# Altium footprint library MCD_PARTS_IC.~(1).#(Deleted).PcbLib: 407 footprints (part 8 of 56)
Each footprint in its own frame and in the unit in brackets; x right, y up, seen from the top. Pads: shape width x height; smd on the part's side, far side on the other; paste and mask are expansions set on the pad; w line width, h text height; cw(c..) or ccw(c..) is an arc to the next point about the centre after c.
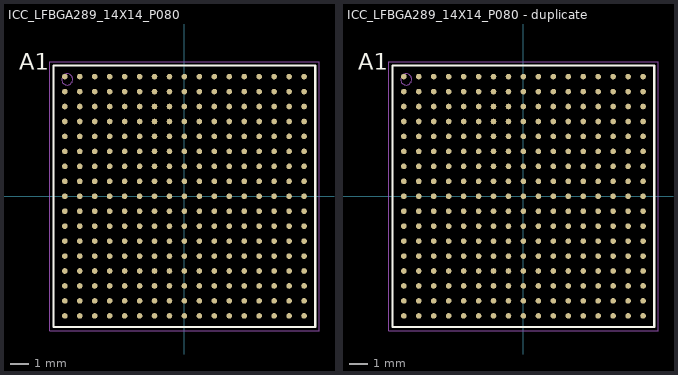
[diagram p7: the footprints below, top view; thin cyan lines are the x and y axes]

## ICC_LFBGA289_14X14_P080 [mm] "MCD-02237"
height 1.7
pads (289):
  round 0.3 smd mask+0.05: A1(-6.4,6.4) A2(-5.6,6.4) A3(-4.8,6.4) A4(-4,6.4) A5(-3.2,6.4) A6(-2.4,6.4) A7(-1.6,6.4) A8(-0.8,6.4) A9(0,6.4) A10(0.8,6.4) A11(1.6,6.4) A12(2.4,6.4) A13(3.2,6.4) A14(4,6.4) A15(4.8,6.4) A16(5.6,6.4) A17(6.4,6.4) B1(-6.4,5.6) B2(-5.6,5.6) B3(-4.8,5.6) B4(-4,5.6) B5(-3.2,5.6) B6(-2.4,5.6) B7(-1.6,5.6) B8(-0.8,5.6) B9(0,5.6) B10(0.8,5.6) B11(1.6,5.6) B12(2.4,5.6) B13(3.2,5.6) B14(4,5.6) B15(4.8,5.6) B16(5.6,5.6) B17(6.4,5.6) C1(-6.4,4.8) C2(-5.6,4.8) C3(-4.8,4.8) C4(-4,4.8) C5(-3.2,4.8) C6(-2.4,4.8) C7(-1.6,4.8) C8(-0.8,4.8) C9(0,4.8) C10(0.8,4.8) C11(1.6,4.8) C12(2.4,4.8) C13(3.2,4.8) C14(4,4.8) C15(4.8,4.8) C16(5.6,4.8) C17(6.4,4.8) D1(-6.4,4) D2(-5.6,4) D3(-4.8,4) D4(-4,4) D5(-3.2,4) D6(-2.4,4) D7(-1.6,4) D8(-0.8,4) D9(0,4) D10(0.8,4) D11(1.6,4) D12(2.4,4) D13(3.2,4) D14(4,4) D15(4.8,4) D16(5.6,4) D17(6.4,4) E1(-6.4,3.2) E2(-5.6,3.2) E3(-4.8,3.2) E4(-4,3.2) E5(-3.2,3.2) E6(-2.4,3.2) E7(-1.6,3.2) E8(-0.8,3.2) E9(0,3.2) E10(0.8,3.2) E11(1.6,3.2) E12(2.4,3.2) E13(3.2,3.2) E14(4,3.2) E15(4.8,3.2) E16(5.6,3.2) E17(6.4,3.2) F1(-6.4,2.4) F2(-5.6,2.4) F3(-4.8,2.4) F4(-4,2.4) F5(-3.2,2.4) F6(-2.4,2.4) F7(-1.6,2.4) F8(-0.8,2.4) F9(0,2.4) F10(0.8,2.4) F11(1.6,2.4) F12(2.4,2.4) F13(3.2,2.4) F14(4,2.4) F15(4.8,2.4) F16(5.6,2.4) F17(6.4,2.4) G1(-6.4,1.6) G2(-5.6,1.6) G3(-4.8,1.6) G4(-4,1.6) G5(-3.2,1.6) G6(-2.4,1.6) G7(-1.6,1.6) G8(-0.8,1.6) G9(0,1.6) G10(0.8,1.6) G11(1.6,1.6) G12(2.4,1.6) G13(3.2,1.6) G14(4,1.6) G15(4.8,1.6) G16(5.6,1.6) G17(6.4,1.6) H1(-6.4,0.8) H2(-5.6,0.8) H3(-4.8,0.8) H4(-4,0.8) H5(-3.2,0.8) H6(-2.4,0.8) H7(-1.6,0.8) H8(-0.8,0.8) H9(0,0.8) H10(0.8,0.8) H11(1.6,0.8) H12(2.4,0.8) H13(3.2,0.8) H14(4,0.8) H15(4.8,0.8) H16(5.6,0.8) H17(6.4,0.8) J1(-6.4,0) J2(-5.6,0) J3(-4.8,0) J4(-4,0) J5(-3.2,0) J6(-2.4,0) J7(-1.6,0) J8(-0.8,0) J9(0,0) J10(0.8,0) J11(1.6,0) J12(2.4,0) J13(3.2,0) J14(4,0) J15(4.8,0) J16(5.6,0) J17(6.4,0) K1(-6.4,-0.8) K2(-5.6,-0.8) K3(-4.8,-0.8) K4(-4,-0.8) K5(-3.2,-0.8) K6(-2.4,-0.8) K7(-1.6,-0.8) K8(-0.8,-0.8) K9(0,-0.8) K10(0.8,-0.8) K11(1.6,-0.8) K12(2.4,-0.8) K13(3.2,-0.8) K14(4,-0.8) K15(4.8,-0.8) K16(5.6,-0.8) K17(6.4,-0.8) L1(-6.4,-1.6) L2(-5.6,-1.6) L3(-4.8,-1.6) L4(-4,-1.6) L5(-3.2,-1.6) L6(-2.4,-1.6) L7(-1.6,-1.6) L8(-0.8,-1.6) L9(0,-1.6) L10(0.8,-1.6) L11(1.6,-1.6) L12(2.4,-1.6) L13(3.2,-1.6) L14(4,-1.6) L15(4.8,-1.6) L16(5.6,-1.6) L17(6.4,-1.6) M1(-6.4,-2.4) M2(-5.6,-2.4) M3(-4.8,-2.4) M4(-4,-2.4) M5(-3.2,-2.4) M6(-2.4,-2.4) M7(-1.6,-2.4) M8(-0.8,-2.4) M9(0,-2.4) M10(0.8,-2.4) M11(1.6,-2.4) M12(2.4,-2.4) M13(3.2,-2.4) M14(4,-2.4) M15(4.8,-2.4) M16(5.6,-2.4) M17(6.4,-2.4) N1(-6.4,-3.2) N2(-5.6,-3.2) N3(-4.8,-3.2) N4(-4,-3.2) N5(-3.2,-3.2) N6(-2.4,-3.2) N7(-1.6,-3.2) N8(-0.8,-3.2) N9(0,-3.2) N10(0.8,-3.2) N11(1.6,-3.2) N12(2.4,-3.2) N13(3.2,-3.2) N14(4,-3.2) N15(4.8,-3.2) N16(5.6,-3.2) N17(6.4,-3.2) P1(-6.4,-4) P2(-5.6,-4) P3(-4.8,-4) P4(-4,-4) P5(-3.2,-4) P6(-2.4,-4) P7(-1.6,-4) P8(-0.8,-4) P9(0,-4) P10(0.8,-4) P11(1.6,-4) P12(2.4,-4) P13(3.2,-4) P14(4,-4) P15(4.8,-4) P16(5.6,-4) P17(6.4,-4) R1(-6.4,-4.8) R2(-5.6,-4.8) R3(-4.8,-4.8) R4(-4,-4.8) R5(-3.2,-4.8) R6(-2.4,-4.8) R7(-1.6,-4.8) R8(-0.8,-4.8) R9(0,-4.8) R10(0.8,-4.8) R11(1.6,-4.8) R12(2.4,-4.8) R13(3.2,-4.8) R14(4,-4.8) R15(4.8,-4.8) R16(5.6,-4.8) R17(6.4,-4.8) T1(-6.4,-5.6) T2(-5.6,-5.6) T3(-4.8,-5.6) T4(-4,-5.6) T5(-3.2,-5.6) T6(-2.4,-5.6) T7(-1.6,-5.6) T8(-0.8,-5.6) T9(0,-5.6) T10(0.8,-5.6) T11(1.6,-5.6) T12(2.4,-5.6) T13(3.2,-5.6) T14(4,-5.6) T15(4.8,-5.6) T16(5.6,-5.6) T17(6.4,-5.6) U1(-6.4,-6.4) U2(-5.6,-6.4) U3(-4.8,-6.4) U4(-4,-6.4) U5(-3.2,-6.4) U6(-2.4,-6.4) U7(-1.6,-6.4) U8(-0.8,-6.4) U9(0,-6.4) U10(0.8,-6.4) U11(1.6,-6.4) U12(2.4,-6.4) U13(3.2,-6.4) U14(4,-6.4) U15(4.8,-6.4) U16(5.6,-6.4) u17(6.4,-6.4)
Top Overlay:
  lines w0.12: -7,-7 7,-7 7,7 -7,7 -7,-7
  text "A1" at -8.85,6.475 h1.5
M14-Top Assembly:
  circle w0.01: c-6.275,6.25 r0.3
  lines w0.01: -7,-7 7,-7 7,7 -7,7 -7,-7
  text "'.Designator'" at -2,-0.5 h0.75
M16-Top Courtyard:
  lines w0.01: -7.2,-7.2 -7.2,7.2 7.2,7.2 7.2,-7.2 -7.2,-7.2
3D body: height 0.4, standoff 0, extent 6.201,-6.597 6.6,-6.203
3D body: height 0.4, standoff 0, extent 5.401,-6.597 5.8,-6.203
3D body: height 0.4, standoff 0, extent 4.601,-6.597 5,-6.203
3D body: height 0.4, standoff 0, extent 3.801,-6.597 4.2,-6.203
3D body: height 0.4, standoff 0, extent 3.001,-6.597 3.4,-6.203
3D body: height 0.4, standoff 0, extent 2.201,-6.597 2.6,-6.203
3D body: height 0.4, standoff 0, extent 1.401,-6.597 1.8,-6.203
3D body: height 0.4, standoff 0, extent 0.601,-6.597 1,-6.203
3D body: height 0.4, standoff 0, extent -0.199,-6.597 0.2,-6.203
3D body: height 0.4, standoff 0, extent -0.999,-6.597 -0.6,-6.203
3D body: height 0.4, standoff 0, extent -1.799,-6.597 -1.4,-6.203
3D body: height 0.4, standoff 0, extent -2.599,-6.597 -2.2,-6.203
3D body: height 0.4, standoff 0, extent -3.399,-6.597 -3,-6.203
3D body: height 0.4, standoff 0, extent -4.199,-6.597 -3.8,-6.203
3D body: height 0.4, standoff 0, extent -4.999,-6.597 -4.6,-6.203
3D body: height 0.4, standoff 0, extent -5.799,-6.597 -5.4,-6.203
3D body: height 0.4, standoff 0, extent -6.599,-6.597 -6.2,-6.203
3D body: height 0.4, standoff 0, extent 6.201,-5.797 6.6,-5.403
3D body: height 0.4, standoff 0, extent 5.401,-5.797 5.8,-5.403
3D body: height 0.4, standoff 0, extent 4.601,-5.797 5,-5.403
3D body: height 0.4, standoff 0, extent 3.801,-5.797 4.2,-5.403
3D body: height 0.4, standoff 0, extent 3.001,-5.797 3.4,-5.403
3D body: height 0.4, standoff 0, extent 2.201,-5.797 2.6,-5.403
3D body: height 0.4, standoff 0, extent 1.401,-5.797 1.8,-5.403
3D body: height 0.4, standoff 0, extent 0.601,-5.797 1,-5.403
3D body: height 0.4, standoff 0, extent -0.199,-5.797 0.2,-5.403
3D body: height 0.4, standoff 0, extent -0.999,-5.797 -0.6,-5.403
3D body: height 0.4, standoff 0, extent -1.799,-5.797 -1.4,-5.403
3D body: height 0.4, standoff 0, extent -2.599,-5.797 -2.2,-5.403
3D body: height 0.4, standoff 0, extent -3.399,-5.797 -3,-5.403
3D body: height 0.4, standoff 0, extent -4.199,-5.797 -3.8,-5.403
3D body: height 0.4, standoff 0, extent -4.999,-5.797 -4.6,-5.403
3D body: height 0.4, standoff 0, extent -5.799,-5.797 -5.4,-5.403
3D body: height 0.4, standoff 0, extent -6.599,-5.797 -6.2,-5.403
3D body: height 0.4, standoff 0, extent 6.201,-4.997 6.6,-4.603
3D body: height 0.4, standoff 0, extent 5.401,-4.997 5.8,-4.603
3D body: height 0.4, standoff 0, extent 4.601,-4.997 5,-4.603
3D body: height 0.4, standoff 0, extent 3.801,-4.997 4.2,-4.603
3D body: height 0.4, standoff 0, extent 3.001,-4.997 3.4,-4.603
3D body: height 0.4, standoff 0, extent 2.201,-4.997 2.6,-4.603
3D body: height 0.4, standoff 0, extent 1.401,-4.997 1.8,-4.603
3D body: height 0.4, standoff 0, extent 0.601,-4.997 1,-4.603
3D body: height 0.4, standoff 0, extent -0.199,-4.997 0.2,-4.603
3D body: height 0.4, standoff 0, extent -0.999,-4.997 -0.6,-4.603
3D body: height 0.4, standoff 0, extent -1.799,-4.997 -1.4,-4.603
3D body: height 0.4, standoff 0, extent -2.599,-4.997 -2.2,-4.603
3D body: height 0.4, standoff 0, extent -3.399,-4.997 -3,-4.603
3D body: height 0.4, standoff 0, extent -4.199,-4.997 -3.8,-4.603
3D body: height 0.4, standoff 0, extent -4.999,-4.997 -4.6,-4.603
3D body: height 0.4, standoff 0, extent -5.799,-4.997 -5.4,-4.603
3D body: height 0.4, standoff 0, extent -6.599,-4.997 -6.2,-4.603
3D body: height 0.4, standoff 0, extent 6.201,-4.197 6.6,-3.803
3D body: height 0.4, standoff 0, extent 5.401,-4.197 5.8,-3.803
3D body: height 0.4, standoff 0, extent 4.601,-4.197 5,-3.803
3D body: height 0.4, standoff 0, extent 3.801,-4.197 4.2,-3.803
3D body: height 0.4, standoff 0, extent 3.001,-4.197 3.4,-3.803
3D body: height 0.4, standoff 0, extent 2.201,-4.197 2.6,-3.803
3D body: height 0.4, standoff 0, extent 1.401,-4.197 1.8,-3.803
3D body: height 0.4, standoff 0, extent 0.601,-4.197 1,-3.803
3D body: height 0.4, standoff 0, extent -0.199,-4.197 0.2,-3.803
3D body: height 0.4, standoff 0, extent -0.999,-4.197 -0.6,-3.803
3D body: height 0.4, standoff 0, extent -1.799,-4.197 -1.4,-3.803
3D body: height 0.4, standoff 0, extent -2.599,-4.197 -2.2,-3.803
3D body: height 0.4, standoff 0, extent -3.399,-4.197 -3,-3.803
3D body: height 0.4, standoff 0, extent -4.199,-4.197 -3.8,-3.803
3D body: height 0.4, standoff 0, extent -4.999,-4.197 -4.6,-3.803
3D body: height 0.4, standoff 0, extent -5.799,-4.197 -5.4,-3.803
3D body: height 0.4, standoff 0, extent -6.599,-4.197 -6.2,-3.803
3D body: height 0.4, standoff 0, extent 6.201,-3.397 6.6,-3.003
3D body: height 0.4, standoff 0, extent 5.401,-3.397 5.8,-3.003
3D body: height 0.4, standoff 0, extent 4.601,-3.397 5,-3.003
3D body: height 0.4, standoff 0, extent 3.801,-3.397 4.2,-3.003
3D body: height 0.4, standoff 0, extent 3.001,-3.397 3.4,-3.003
3D body: height 0.4, standoff 0, extent 2.201,-3.397 2.6,-3.003
3D body: height 0.4, standoff 0, extent 1.401,-3.397 1.8,-3.003
3D body: height 0.4, standoff 0, extent 0.601,-3.397 1,-3.003
3D body: height 0.4, standoff 0, extent -0.199,-3.397 0.2,-3.003
3D body: height 0.4, standoff 0, extent -0.999,-3.397 -0.6,-3.003
3D body: height 0.4, standoff 0, extent -1.799,-3.397 -1.4,-3.003
3D body: height 0.4, standoff 0, extent -2.599,-3.397 -2.2,-3.003
3D body: height 0.4, standoff 0, extent -3.399,-3.397 -3,-3.003
3D body: height 0.4, standoff 0, extent -4.199,-3.397 -3.8,-3.003
3D body: height 0.4, standoff 0, extent -4.999,-3.397 -4.6,-3.003
3D body: height 0.4, standoff 0, extent -5.799,-3.397 -5.4,-3.003
3D body: height 0.4, standoff 0, extent -6.599,-3.397 -6.2,-3.003
3D body: height 0.4, standoff 0, extent 6.201,-2.597 6.6,-2.203
3D body: height 0.4, standoff 0, extent 5.401,-2.597 5.8,-2.203
3D body: height 0.4, standoff 0, extent 4.601,-2.597 5,-2.203
3D body: height 0.4, standoff 0, extent 3.801,-2.597 4.2,-2.203
3D body: height 0.4, standoff 0, extent 3.001,-2.597 3.4,-2.203
3D body: height 0.4, standoff 0, extent 2.201,-2.597 2.6,-2.203
3D body: height 0.4, standoff 0, extent 1.401,-2.597 1.8,-2.203
3D body: height 0.4, standoff 0, extent 0.601,-2.597 1,-2.203
3D body: height 0.4, standoff 0, extent -0.199,-2.597 0.2,-2.203
3D body: height 0.4, standoff 0, extent -0.999,-2.597 -0.6,-2.203
3D body: height 0.4, standoff 0, extent -1.799,-2.597 -1.4,-2.203
3D body: height 0.4, standoff 0, extent -2.599,-2.597 -2.2,-2.203
3D body: height 0.4, standoff 0, extent -3.399,-2.597 -3,-2.203
3D body: height 0.4, standoff 0, extent -4.199,-2.597 -3.8,-2.203
3D body: height 0.4, standoff 0, extent -4.999,-2.597 -4.6,-2.203
3D body: height 0.4, standoff 0, extent -5.799,-2.597 -5.4,-2.203
3D body: height 0.4, standoff 0, extent -6.599,-2.597 -6.2,-2.203
3D body: height 0.4, standoff 0, extent 6.201,-1.797 6.6,-1.403
3D body: height 0.4, standoff 0, extent 5.401,-1.797 5.8,-1.403
3D body: height 0.4, standoff 0, extent 4.601,-1.797 5,-1.403
3D body: height 0.4, standoff 0, extent 3.801,-1.797 4.2,-1.403
3D body: height 0.4, standoff 0, extent 3.001,-1.797 3.4,-1.403
3D body: height 0.4, standoff 0, extent 2.201,-1.797 2.6,-1.403
3D body: height 0.4, standoff 0, extent 1.401,-1.797 1.8,-1.403
3D body: height 0.4, standoff 0, extent 0.601,-1.797 1,-1.403
3D body: height 0.4, standoff 0, extent -0.199,-1.797 0.2,-1.403
3D body: height 0.4, standoff 0, extent -0.999,-1.797 -0.6,-1.403
3D body: height 0.4, standoff 0, extent -1.799,-1.797 -1.4,-1.403
3D body: height 0.4, standoff 0, extent -2.599,-1.797 -2.2,-1.403
3D body: height 0.4, standoff 0, extent -3.399,-1.797 -3,-1.403
3D body: height 0.4, standoff 0, extent -4.199,-1.797 -3.8,-1.403
3D body: height 0.4, standoff 0, extent -4.999,-1.797 -4.6,-1.403
3D body: height 0.4, standoff 0, extent -5.799,-1.797 -5.4,-1.403
3D body: height 0.4, standoff 0, extent -6.599,-1.797 -6.2,-1.403
3D body: height 0.4, standoff 0, extent 6.201,-0.997 6.6,-0.603
3D body: height 0.4, standoff 0, extent 5.401,-0.997 5.8,-0.603
3D body: height 0.4, standoff 0, extent 4.601,-0.997 5,-0.603
3D body: height 0.4, standoff 0, extent 3.801,-0.997 4.2,-0.603
3D body: height 0.4, standoff 0, extent 3.001,-0.997 3.4,-0.603
3D body: height 0.4, standoff 0, extent 2.201,-0.997 2.6,-0.603
3D body: height 0.4, standoff 0, extent 1.401,-0.997 1.8,-0.603
3D body: height 0.4, standoff 0, extent 0.601,-0.997 1,-0.603
3D body: height 0.4, standoff 0, extent -0.199,-0.997 0.2,-0.603
3D body: height 0.4, standoff 0, extent -0.999,-0.997 -0.6,-0.603
3D body: height 0.4, standoff 0, extent -1.799,-0.997 -1.4,-0.603
3D body: height 0.4, standoff 0, extent -2.599,-0.997 -2.2,-0.603
3D body: height 0.4, standoff 0, extent -3.399,-0.997 -3,-0.603
3D body: height 0.4, standoff 0, extent -4.199,-0.997 -3.8,-0.603
3D body: height 0.4, standoff 0, extent -4.999,-0.997 -4.6,-0.603
3D body: height 0.4, standoff 0, extent -5.799,-0.997 -5.4,-0.603
3D body: height 0.4, standoff 0, extent -6.599,-0.997 -6.2,-0.603
3D body: height 0.4, standoff 0, extent 6.201,-0.197 6.6,0.197
3D body: height 0.4, standoff 0, extent 5.401,-0.197 5.8,0.197
3D body: height 0.4, standoff 0, extent 4.601,-0.197 5,0.197
3D body: height 0.4, standoff 0, extent 3.801,-0.197 4.2,0.197
3D body: height 0.4, standoff 0, extent 3.001,-0.197 3.4,0.197
3D body: height 0.4, standoff 0, extent 2.201,-0.197 2.6,0.197
3D body: height 0.4, standoff 0, extent 1.401,-0.197 1.8,0.197
3D body: height 0.4, standoff 0, extent 0.601,-0.197 1,0.197
3D body: height 0.4, standoff 0, extent -0.199,-0.197 0.2,0.197
3D body: height 0.4, standoff 0, extent -0.999,-0.197 -0.6,0.197
3D body: height 0.4, standoff 0, extent -1.799,-0.197 -1.4,0.197
3D body: height 0.4, standoff 0, extent -2.599,-0.197 -2.2,0.197
3D body: height 0.4, standoff 0, extent -3.399,-0.197 -3,0.197
3D body: height 0.4, standoff 0, extent -4.199,-0.197 -3.8,0.197
3D body: height 0.4, standoff 0, extent -4.999,-0.197 -4.6,0.197
3D body: height 0.4, standoff 0, extent -5.799,-0.197 -5.4,0.197
3D body: height 0.4, standoff 0, extent -6.599,-0.197 -6.2,0.197
3D body: height 0.4, standoff 0, extent 6.201,0.603 6.6,0.997
3D body: height 0.4, standoff 0, extent 5.401,0.603 5.8,0.997
3D body: height 0.4, standoff 0, extent 4.601,0.603 5,0.997
3D body: height 0.4, standoff 0, extent 3.801,0.603 4.2,0.997
3D body: height 0.4, standoff 0, extent 3.001,0.603 3.4,0.997
3D body: height 0.4, standoff 0, extent 2.201,0.603 2.6,0.997
3D body: height 0.4, standoff 0, extent 1.401,0.603 1.8,0.997
3D body: height 0.4, standoff 0, extent 0.601,0.603 1,0.997
3D body: height 0.4, standoff 0, extent -0.199,0.603 0.2,0.997
3D body: height 0.4, standoff 0, extent -0.999,0.603 -0.6,0.997
3D body: height 0.4, standoff 0, extent -1.799,0.603 -1.4,0.997
3D body: height 0.4, standoff 0, extent -2.599,0.603 -2.2,0.997
3D body: height 0.4, standoff 0, extent -3.399,0.603 -3,0.997
3D body: height 0.4, standoff 0, extent -4.199,0.603 -3.8,0.997
3D body: height 0.4, standoff 0, extent -4.999,0.603 -4.6,0.997
3D body: height 0.4, standoff 0, extent -5.799,0.603 -5.4,0.997
3D body: height 0.4, standoff 0, extent -6.599,0.603 -6.2,0.997
3D body: height 0.4, standoff 0, extent 6.201,1.403 6.6,1.797
3D body: height 0.4, standoff 0, extent 5.401,1.403 5.8,1.797
3D body: height 0.4, standoff 0, extent 4.601,1.403 5,1.797
3D body: height 0.4, standoff 0, extent 3.801,1.403 4.2,1.797
3D body: height 0.4, standoff 0, extent 3.001,1.403 3.4,1.797
3D body: height 0.4, standoff 0, extent 2.201,1.403 2.6,1.797
3D body: height 0.4, standoff 0, extent 1.401,1.403 1.8,1.797
3D body: height 0.4, standoff 0, extent 0.601,1.403 1,1.797
3D body: height 0.4, standoff 0, extent -0.199,1.403 0.2,1.797
3D body: height 0.4, standoff 0, extent -0.999,1.403 -0.6,1.797
3D body: height 0.4, standoff 0, extent -1.799,1.403 -1.4,1.797
3D body: height 0.4, standoff 0, extent -2.599,1.403 -2.2,1.797
3D body: height 0.4, standoff 0, extent -3.399,1.403 -3,1.797
3D body: height 0.4, standoff 0, extent -4.199,1.403 -3.8,1.797
3D body: height 0.4, standoff 0, extent -4.999,1.403 -4.6,1.797
3D body: height 0.4, standoff 0, extent -5.799,1.403 -5.4,1.797
3D body: height 0.4, standoff 0, extent -6.599,1.403 -6.2,1.797
3D body: height 0.4, standoff 0, extent 6.201,2.203 6.6,2.597
3D body: height 0.4, standoff 0, extent 5.401,2.203 5.8,2.597
3D body: height 0.4, standoff 0, extent 4.601,2.203 5,2.597
3D body: height 0.4, standoff 0, extent 3.801,2.203 4.2,2.597
3D body: height 0.4, standoff 0, extent 3.001,2.203 3.4,2.597
3D body: height 0.4, standoff 0, extent 2.201,2.203 2.6,2.597
3D body: height 0.4, standoff 0, extent 1.401,2.203 1.8,2.597
3D body: height 0.4, standoff 0, extent 0.601,2.203 1,2.597
3D body: height 0.4, standoff 0, extent -0.199,2.203 0.2,2.597
3D body: height 0.4, standoff 0, extent -0.999,2.203 -0.6,2.597
3D body: height 0.4, standoff 0, extent -1.799,2.203 -1.4,2.597
3D body: height 0.4, standoff 0, extent -2.599,2.203 -2.2,2.597
3D body: height 0.4, standoff 0, extent -3.399,2.203 -3,2.597
3D body: height 0.4, standoff 0, extent -4.199,2.203 -3.8,2.597
3D body: height 0.4, standoff 0, extent -4.999,2.203 -4.6,2.597
3D body: height 0.4, standoff 0, extent -5.799,2.203 -5.4,2.597
3D body: height 0.4, standoff 0, extent -6.599,2.203 -6.2,2.597
3D body: height 0.4, standoff 0, extent 6.201,3.003 6.6,3.397
3D body: height 0.4, standoff 0, extent 5.401,3.003 5.8,3.397
3D body: height 0.4, standoff 0, extent 4.601,3.003 5,3.397
3D body: height 0.4, standoff 0, extent 3.801,3.003 4.2,3.397
3D body: height 0.4, standoff 0, extent 3.001,3.003 3.4,3.397
3D body: height 0.4, standoff 0, extent 2.201,3.003 2.6,3.397
3D body: height 0.4, standoff 0, extent 1.401,3.003 1.8,3.397
3D body: height 0.4, standoff 0, extent 0.601,3.003 1,3.397
3D body: height 0.4, standoff 0, extent -0.199,3.003 0.2,3.397
3D body: height 0.4, standoff 0, extent -0.999,3.003 -0.6,3.397
3D body: height 0.4, standoff 0, extent -1.799,3.003 -1.4,3.397
3D body: height 0.4, standoff 0, extent -2.599,3.003 -2.2,3.397
3D body: height 0.4, standoff 0, extent -3.399,3.003 -3,3.397
3D body: height 0.4, standoff 0, extent -4.199,3.003 -3.8,3.397
3D body: height 0.4, standoff 0, extent -4.999,3.003 -4.6,3.397
3D body: height 0.4, standoff 0, extent -5.799,3.003 -5.4,3.397
3D body: height 0.4, standoff 0, extent -6.599,3.003 -6.2,3.397
3D body: height 0.4, standoff 0, extent 6.201,3.803 6.6,4.197
3D body: height 0.4, standoff 0, extent 5.401,3.803 5.8,4.197
3D body: height 0.4, standoff 0, extent 4.601,3.803 5,4.197
3D body: height 0.4, standoff 0, extent 3.801,3.803 4.2,4.197
3D body: height 0.4, standoff 0, extent 3.001,3.803 3.4,4.197
3D body: height 0.4, standoff 0, extent 2.201,3.803 2.6,4.197
3D body: height 0.4, standoff 0, extent 1.401,3.803 1.8,4.197
3D body: height 0.4, standoff 0, extent 0.601,3.803 1,4.197
3D body: height 0.4, standoff 0, extent -0.199,3.803 0.2,4.197
3D body: height 0.4, standoff 0, extent -0.999,3.803 -0.6,4.197
3D body: height 0.4, standoff 0, extent -1.799,3.803 -1.4,4.197
3D body: height 0.4, standoff 0, extent -2.599,3.803 -2.2,4.197
3D body: height 0.4, standoff 0, extent -3.399,3.803 -3,4.197
3D body: height 0.4, standoff 0, extent -4.199,3.803 -3.8,4.197
3D body: height 0.4, standoff 0, extent -4.999,3.803 -4.6,4.197
3D body: height 0.4, standoff 0, extent -5.799,3.803 -5.4,4.197
3D body: height 0.4, standoff 0, extent -6.599,3.803 -6.2,4.197
3D body: height 0.4, standoff 0, extent 6.201,4.603 6.6,4.997
3D body: height 0.4, standoff 0, extent 5.401,4.603 5.8,4.997
3D body: height 0.4, standoff 0, extent 4.601,4.603 5,4.997
3D body: height 0.4, standoff 0, extent 3.801,4.603 4.2,4.997
3D body: height 0.4, standoff 0, extent 3.001,4.603 3.4,4.997
3D body: height 0.4, standoff 0, extent 2.201,4.603 2.6,4.997
3D body: height 0.4, standoff 0, extent 1.401,4.603 1.8,4.997
3D body: height 0.4, standoff 0, extent 0.601,4.603 1,4.997
3D body: height 0.4, standoff 0, extent -0.199,4.603 0.2,4.997
3D body: height 0.4, standoff 0, extent -0.999,4.603 -0.6,4.997
3D body: height 0.4, standoff 0, extent -1.799,4.603 -1.4,4.997
3D body: height 0.4, standoff 0, extent -2.599,4.603 -2.2,4.997
3D body: height 0.4, standoff 0, extent -3.399,4.603 -3,4.997
3D body: height 0.4, standoff 0, extent -4.199,4.603 -3.8,4.997
3D body: height 0.4, standoff 0, extent -4.999,4.603 -4.6,4.997
3D body: height 0.4, standoff 0, extent -5.799,4.603 -5.4,4.997
3D body: height 0.4, standoff 0, extent -6.599,4.603 -6.2,4.997
3D body: height 0.4, standoff 0, extent 6.201,5.403 6.6,5.797
3D body: height 0.4, standoff 0, extent 5.401,5.403 5.8,5.797
3D body: height 0.4, standoff 0, extent 4.601,5.403 5,5.797
3D body: height 0.4, standoff 0, extent 3.801,5.403 4.2,5.797
3D body: height 0.4, standoff 0, extent 3.001,5.403 3.4,5.797
3D body: height 0.4, standoff 0, extent 2.201,5.403 2.6,5.797
3D body: height 0.4, standoff 0, extent 1.401,5.403 1.8,5.797
3D body: height 0.4, standoff 0, extent 0.601,5.403 1,5.797
3D body: height 0.4, standoff 0, extent -0.199,5.403 0.2,5.797
3D body: height 0.4, standoff 0, extent -0.999,5.403 -0.6,5.797
3D body: height 0.4, standoff 0, extent -1.799,5.403 -1.4,5.797
3D body: height 0.4, standoff 0, extent -2.599,5.403 -2.2,5.797
3D body: height 0.4, standoff 0, extent -3.399,5.403 -3,5.797
3D body: height 0.4, standoff 0, extent -4.199,5.403 -3.8,5.797
3D body: height 0.4, standoff 0, extent -4.999,5.403 -4.6,5.797
3D body: height 0.4, standoff 0, extent -5.799,5.403 -5.4,5.797
3D body: height 0.4, standoff 0, extent -6.599,5.403 -6.2,5.797
3D body: height 0.4, standoff 0, extent 6.201,6.203 6.6,6.597
3D body: height 0.4, standoff 0, extent 5.401,6.203 5.8,6.597
3D body: height 0.4, standoff 0, extent 4.601,6.203 5,6.597
3D body: height 0.4, standoff 0, extent 3.801,6.203 4.2,6.597
3D body: height 0.4, standoff 0, extent 3.001,6.203 3.4,6.597
3D body: height 0.4, standoff 0, extent 2.201,6.203 2.6,6.597
3D body: height 0.4, standoff 0, extent 1.401,6.203 1.8,6.597
3D body: height 0.4, standoff 0, extent 0.601,6.203 1,6.597
3D body: height 0.4, standoff 0, extent -0.199,6.203 0.2,6.597
3D body: height 0.4, standoff 0, extent -0.999,6.203 -0.6,6.597
3D body: height 0.4, standoff 0, extent -1.799,6.203 -1.4,6.597
3D body: height 0.4, standoff 0, extent -2.599,6.203 -2.2,6.597
3D body: height 0.4, standoff 0, extent -3.399,6.203 -3,6.597
3D body: height 0.4, standoff 0, extent -4.199,6.203 -3.8,6.597
3D body: height 0.4, standoff 0, extent -4.999,6.203 -4.6,6.597
3D body: height 0.4, standoff 0, extent -5.799,6.203 -5.4,6.597
3D body: height 0.4, standoff 0, extent -6.599,6.203 -6.2,6.597
3D body: height 1.71, standoff 1.7, extent -6.672,5.851 -5.875,6.649
3D body: height 1.7, standoff 0.29, extent -7,-7 7,7

## ICC_LFBGA289_14X14_P080 - duplicate [mm] "MCD-02237"
height 1.7
pads (289):
  round 0.3 smd mask+0.05: A1(-6.4,6.4) A2(-5.6,6.4) A3(-4.8,6.4) A4(-4,6.4) A5(-3.2,6.4) A6(-2.4,6.4) A7(-1.6,6.4) A8(-0.8,6.4) A9(0,6.4) A10(0.8,6.4) A11(1.6,6.4) A12(2.4,6.4) A13(3.2,6.4) A14(4,6.4) A15(4.8,6.4) A16(5.6,6.4) A17(6.4,6.4) B1(-6.4,5.6) B2(-5.6,5.6) B3(-4.8,5.6) B4(-4,5.6) B5(-3.2,5.6) B6(-2.4,5.6) B7(-1.6,5.6) B8(-0.8,5.6) B9(0,5.6) B10(0.8,5.6) B11(1.6,5.6) B12(2.4,5.6) B13(3.2,5.6) B14(4,5.6) B15(4.8,5.6) B16(5.6,5.6) B17(6.4,5.6) C1(-6.4,4.8) C2(-5.6,4.8) C3(-4.8,4.8) C4(-4,4.8) C5(-3.2,4.8) C6(-2.4,4.8) C7(-1.6,4.8) C8(-0.8,4.8) C9(0,4.8) C10(0.8,4.8) C11(1.6,4.8) C12(2.4,4.8) C13(3.2,4.8) C14(4,4.8) C15(4.8,4.8) C16(5.6,4.8) C17(6.4,4.8) D1(-6.4,4) D2(-5.6,4) D3(-4.8,4) D4(-4,4) D5(-3.2,4) D6(-2.4,4) D7(-1.6,4) D8(-0.8,4) D9(0,4) D10(0.8,4) D11(1.6,4) D12(2.4,4) D13(3.2,4) D14(4,4) D15(4.8,4) D16(5.6,4) D17(6.4,4) E1(-6.4,3.2) E2(-5.6,3.2) E3(-4.8,3.2) E4(-4,3.2) E5(-3.2,3.2) E6(-2.4,3.2) E7(-1.6,3.2) E8(-0.8,3.2) E9(0,3.2) E10(0.8,3.2) E11(1.6,3.2) E12(2.4,3.2) E13(3.2,3.2) E14(4,3.2) E15(4.8,3.2) E16(5.6,3.2) E17(6.4,3.2) F1(-6.4,2.4) F2(-5.6,2.4) F3(-4.8,2.4) F4(-4,2.4) F5(-3.2,2.4) F6(-2.4,2.4) F7(-1.6,2.4) F8(-0.8,2.4) F9(0,2.4) F10(0.8,2.4) F11(1.6,2.4) F12(2.4,2.4) F13(3.2,2.4) F14(4,2.4) F15(4.8,2.4) F16(5.6,2.4) F17(6.4,2.4) G1(-6.4,1.6) G2(-5.6,1.6) G3(-4.8,1.6) G4(-4,1.6) G5(-3.2,1.6) G6(-2.4,1.6) G7(-1.6,1.6) G8(-0.8,1.6) G9(0,1.6) G10(0.8,1.6) G11(1.6,1.6) G12(2.4,1.6) G13(3.2,1.6) G14(4,1.6) G15(4.8,1.6) G16(5.6,1.6) G17(6.4,1.6) H1(-6.4,0.8) H2(-5.6,0.8) H3(-4.8,0.8) H4(-4,0.8) H5(-3.2,0.8) H6(-2.4,0.8) H7(-1.6,0.8) H8(-0.8,0.8) H9(0,0.8) H10(0.8,0.8) H11(1.6,0.8) H12(2.4,0.8) H13(3.2,0.8) H14(4,0.8) H15(4.8,0.8) H16(5.6,0.8) H17(6.4,0.8) J1(-6.4,0) J2(-5.6,0) J3(-4.8,0) J4(-4,0) J5(-3.2,0) J6(-2.4,0) J7(-1.6,0) J8(-0.8,0) J9(0,0) J10(0.8,0) J11(1.6,0) J12(2.4,0) J13(3.2,0) J14(4,0) J15(4.8,0) J16(5.6,0) J17(6.4,0) K1(-6.4,-0.8) K2(-5.6,-0.8) K3(-4.8,-0.8) K4(-4,-0.8) K5(-3.2,-0.8) K6(-2.4,-0.8) K7(-1.6,-0.8) K8(-0.8,-0.8) K9(0,-0.8) K10(0.8,-0.8) K11(1.6,-0.8) K12(2.4,-0.8) K13(3.2,-0.8) K14(4,-0.8) K15(4.8,-0.8) K16(5.6,-0.8) K17(6.4,-0.8) L1(-6.4,-1.6) L2(-5.6,-1.6) L3(-4.8,-1.6) L4(-4,-1.6) L5(-3.2,-1.6) L6(-2.4,-1.6) L7(-1.6,-1.6) L8(-0.8,-1.6) L9(0,-1.6) L10(0.8,-1.6) L11(1.6,-1.6) L12(2.4,-1.6) L13(3.2,-1.6) L14(4,-1.6) L15(4.8,-1.6) L16(5.6,-1.6) L17(6.4,-1.6) M1(-6.4,-2.4) M2(-5.6,-2.4) M3(-4.8,-2.4) M4(-4,-2.4) M5(-3.2,-2.4) M6(-2.4,-2.4) M7(-1.6,-2.4) M8(-0.8,-2.4) M9(0,-2.4) M10(0.8,-2.4) M11(1.6,-2.4) M12(2.4,-2.4) M13(3.2,-2.4) M14(4,-2.4) M15(4.8,-2.4) M16(5.6,-2.4) M17(6.4,-2.4) N1(-6.4,-3.2) N2(-5.6,-3.2) N3(-4.8,-3.2) N4(-4,-3.2) N5(-3.2,-3.2) N6(-2.4,-3.2) N7(-1.6,-3.2) N8(-0.8,-3.2) N9(0,-3.2) N10(0.8,-3.2) N11(1.6,-3.2) N12(2.4,-3.2) N13(3.2,-3.2) N14(4,-3.2) N15(4.8,-3.2) N16(5.6,-3.2) N17(6.4,-3.2) P1(-6.4,-4) P2(-5.6,-4) P3(-4.8,-4) P4(-4,-4) P5(-3.2,-4) P6(-2.4,-4) P7(-1.6,-4) P8(-0.8,-4) P9(0,-4) P10(0.8,-4) P11(1.6,-4) P12(2.4,-4) P13(3.2,-4) P14(4,-4) P15(4.8,-4) P16(5.6,-4) P17(6.4,-4) R1(-6.4,-4.8) R2(-5.6,-4.8) R3(-4.8,-4.8) R4(-4,-4.8) R5(-3.2,-4.8) R6(-2.4,-4.8) R7(-1.6,-4.8) R8(-0.8,-4.8) R9(0,-4.8) R10(0.8,-4.8) R11(1.6,-4.8) R12(2.4,-4.8) R13(3.2,-4.8) R14(4,-4.8) R15(4.8,-4.8) R16(5.6,-4.8) R17(6.4,-4.8) T1(-6.4,-5.6) T2(-5.6,-5.6) T3(-4.8,-5.6) T4(-4,-5.6) T5(-3.2,-5.6) T6(-2.4,-5.6) T7(-1.6,-5.6) T8(-0.8,-5.6) T9(0,-5.6) T10(0.8,-5.6) T11(1.6,-5.6) T12(2.4,-5.6) T13(3.2,-5.6) T14(4,-5.6) T15(4.8,-5.6) T16(5.6,-5.6) T17(6.4,-5.6) U1(-6.4,-6.4) U2(-5.6,-6.4) U3(-4.8,-6.4) U4(-4,-6.4) U5(-3.2,-6.4) U6(-2.4,-6.4) U7(-1.6,-6.4) U8(-0.8,-6.4) U9(0,-6.4) U10(0.8,-6.4) U11(1.6,-6.4) U12(2.4,-6.4) U13(3.2,-6.4) U14(4,-6.4) U15(4.8,-6.4) U16(5.6,-6.4) u17(6.4,-6.4)
Top Overlay:
  lines w0.12: -7,-7 -7,7 7,7 7,-7 -7,-7
  text "A1" at -8.85,6.475 h1.5
M14-Top Assembly:
  circle w0.01: c-6.275,6.25 r0.3
  lines w0.01: -7,-7 -7,7 7,7 7,-7 -7,-7
  text "'.Designator'" at -2,-0.5 h0.75
M16-Top Courtyard:
  lines w0.01: -7.2,-7.2 7.2,-7.2 7.2,7.2 -7.2,7.2 -7.2,-7.2
3D body: height 1.7, standoff 0.29, extent -7,-7 7,7
3D body: height 1.71, standoff 1.7, extent -6.672,5.851 -5.875,6.649
3D body: height 0.4, standoff 0, extent -6.599,6.203 -6.2,6.597
3D body: height 0.4, standoff 0, extent -5.799,6.203 -5.4,6.597
3D body: height 0.4, standoff 0, extent -4.999,6.203 -4.6,6.597
3D body: height 0.4, standoff 0, extent -4.199,6.203 -3.8,6.597
3D body: height 0.4, standoff 0, extent -3.399,6.203 -3,6.597
3D body: height 0.4, standoff 0, extent -2.599,6.203 -2.2,6.597
3D body: height 0.4, standoff 0, extent -1.799,6.203 -1.4,6.597
3D body: height 0.4, standoff 0, extent -0.999,6.203 -0.6,6.597
3D body: height 0.4, standoff 0, extent -0.199,6.203 0.2,6.597
3D body: height 0.4, standoff 0, extent 0.601,6.203 1,6.597
3D body: height 0.4, standoff 0, extent 1.401,6.203 1.8,6.597
3D body: height 0.4, standoff 0, extent 2.201,6.203 2.6,6.597
3D body: height 0.4, standoff 0, extent 3.001,6.203 3.4,6.597
3D body: height 0.4, standoff 0, extent 3.801,6.203 4.2,6.597
3D body: height 0.4, standoff 0, extent 4.601,6.203 5,6.597
3D body: height 0.4, standoff 0, extent 5.401,6.203 5.8,6.597
3D body: height 0.4, standoff 0, extent 6.201,6.203 6.6,6.597
3D body: height 0.4, standoff 0, extent -6.599,5.403 -6.2,5.797
3D body: height 0.4, standoff 0, extent -5.799,5.403 -5.4,5.797
3D body: height 0.4, standoff 0, extent -4.999,5.403 -4.6,5.797
3D body: height 0.4, standoff 0, extent -4.199,5.403 -3.8,5.797
3D body: height 0.4, standoff 0, extent -3.399,5.403 -3,5.797
3D body: height 0.4, standoff 0, extent -2.599,5.403 -2.2,5.797
3D body: height 0.4, standoff 0, extent -1.799,5.403 -1.4,5.797
3D body: height 0.4, standoff 0, extent -0.999,5.403 -0.6,5.797
3D body: height 0.4, standoff 0, extent -0.199,5.403 0.2,5.797
3D body: height 0.4, standoff 0, extent 0.601,5.403 1,5.797
3D body: height 0.4, standoff 0, extent 1.401,5.403 1.8,5.797
3D body: height 0.4, standoff 0, extent 2.201,5.403 2.6,5.797
3D body: height 0.4, standoff 0, extent 3.001,5.403 3.4,5.797
3D body: height 0.4, standoff 0, extent 3.801,5.403 4.2,5.797
3D body: height 0.4, standoff 0, extent 4.601,5.403 5,5.797
3D body: height 0.4, standoff 0, extent 5.401,5.403 5.8,5.797
3D body: height 0.4, standoff 0, extent 6.201,5.403 6.6,5.797
3D body: height 0.4, standoff 0, extent -6.599,4.603 -6.2,4.997
3D body: height 0.4, standoff 0, extent -5.799,4.603 -5.4,4.997
3D body: height 0.4, standoff 0, extent -4.999,4.603 -4.6,4.997
3D body: height 0.4, standoff 0, extent -4.199,4.603 -3.8,4.997
3D body: height 0.4, standoff 0, extent -3.399,4.603 -3,4.997
3D body: height 0.4, standoff 0, extent -2.599,4.603 -2.2,4.997
3D body: height 0.4, standoff 0, extent -1.799,4.603 -1.4,4.997
3D body: height 0.4, standoff 0, extent -0.999,4.603 -0.6,4.997
3D body: height 0.4, standoff 0, extent -0.199,4.603 0.2,4.997
3D body: height 0.4, standoff 0, extent 0.601,4.603 1,4.997
3D body: height 0.4, standoff 0, extent 1.401,4.603 1.8,4.997
3D body: height 0.4, standoff 0, extent 2.201,4.603 2.6,4.997
3D body: height 0.4, standoff 0, extent 3.001,4.603 3.4,4.997
3D body: height 0.4, standoff 0, extent 3.801,4.603 4.2,4.997
3D body: height 0.4, standoff 0, extent 4.601,4.603 5,4.997
3D body: height 0.4, standoff 0, extent 5.401,4.603 5.8,4.997
3D body: height 0.4, standoff 0, extent 6.201,4.603 6.6,4.997
3D body: height 0.4, standoff 0, extent -6.599,3.803 -6.2,4.197
3D body: height 0.4, standoff 0, extent -5.799,3.803 -5.4,4.197
3D body: height 0.4, standoff 0, extent -4.999,3.803 -4.6,4.197
3D body: height 0.4, standoff 0, extent -4.199,3.803 -3.8,4.197
3D body: height 0.4, standoff 0, extent -3.399,3.803 -3,4.197
3D body: height 0.4, standoff 0, extent -2.599,3.803 -2.2,4.197
3D body: height 0.4, standoff 0, extent -1.799,3.803 -1.4,4.197
3D body: height 0.4, standoff 0, extent -0.999,3.803 -0.6,4.197
3D body: height 0.4, standoff 0, extent -0.199,3.803 0.2,4.197
3D body: height 0.4, standoff 0, extent 0.601,3.803 1,4.197
3D body: height 0.4, standoff 0, extent 1.401,3.803 1.8,4.197
3D body: height 0.4, standoff 0, extent 2.201,3.803 2.6,4.197
3D body: height 0.4, standoff 0, extent 3.001,3.803 3.4,4.197
3D body: height 0.4, standoff 0, extent 3.801,3.803 4.2,4.197
3D body: height 0.4, standoff 0, extent 4.601,3.803 5,4.197
3D body: height 0.4, standoff 0, extent 5.401,3.803 5.8,4.197
3D body: height 0.4, standoff 0, extent 6.201,3.803 6.6,4.197
3D body: height 0.4, standoff 0, extent -6.599,3.003 -6.2,3.397
3D body: height 0.4, standoff 0, extent -5.799,3.003 -5.4,3.397
3D body: height 0.4, standoff 0, extent -4.999,3.003 -4.6,3.397
3D body: height 0.4, standoff 0, extent -4.199,3.003 -3.8,3.397
3D body: height 0.4, standoff 0, extent -3.399,3.003 -3,3.397
3D body: height 0.4, standoff 0, extent -2.599,3.003 -2.2,3.397
3D body: height 0.4, standoff 0, extent -1.799,3.003 -1.4,3.397
3D body: height 0.4, standoff 0, extent -0.999,3.003 -0.6,3.397
3D body: height 0.4, standoff 0, extent -0.199,3.003 0.2,3.397
3D body: height 0.4, standoff 0, extent 0.601,3.003 1,3.397
3D body: height 0.4, standoff 0, extent 1.401,3.003 1.8,3.397
3D body: height 0.4, standoff 0, extent 2.201,3.003 2.6,3.397
3D body: height 0.4, standoff 0, extent 3.001,3.003 3.4,3.397
3D body: height 0.4, standoff 0, extent 3.801,3.003 4.2,3.397
3D body: height 0.4, standoff 0, extent 4.601,3.003 5,3.397
3D body: height 0.4, standoff 0, extent 5.401,3.003 5.8,3.397
3D body: height 0.4, standoff 0, extent 6.201,3.003 6.6,3.397
3D body: height 0.4, standoff 0, extent -6.599,2.203 -6.2,2.597
3D body: height 0.4, standoff 0, extent -5.799,2.203 -5.4,2.597
3D body: height 0.4, standoff 0, extent -4.999,2.203 -4.6,2.597
3D body: height 0.4, standoff 0, extent -4.199,2.203 -3.8,2.597
3D body: height 0.4, standoff 0, extent -3.399,2.203 -3,2.597
3D body: height 0.4, standoff 0, extent -2.599,2.203 -2.2,2.597
3D body: height 0.4, standoff 0, extent -1.799,2.203 -1.4,2.597
3D body: height 0.4, standoff 0, extent -0.999,2.203 -0.6,2.597
3D body: height 0.4, standoff 0, extent -0.199,2.203 0.2,2.597
3D body: height 0.4, standoff 0, extent 0.601,2.203 1,2.597
3D body: height 0.4, standoff 0, extent 1.401,2.203 1.8,2.597
3D body: height 0.4, standoff 0, extent 2.201,2.203 2.6,2.597
3D body: height 0.4, standoff 0, extent 3.001,2.203 3.4,2.597
3D body: height 0.4, standoff 0, extent 3.801,2.203 4.2,2.597
3D body: height 0.4, standoff 0, extent 4.601,2.203 5,2.597
3D body: height 0.4, standoff 0, extent 5.401,2.203 5.8,2.597
3D body: height 0.4, standoff 0, extent 6.201,2.203 6.6,2.597
3D body: height 0.4, standoff 0, extent -6.599,1.403 -6.2,1.797
3D body: height 0.4, standoff 0, extent -5.799,1.403 -5.4,1.797
3D body: height 0.4, standoff 0, extent -4.999,1.403 -4.6,1.797
3D body: height 0.4, standoff 0, extent -4.199,1.403 -3.8,1.797
3D body: height 0.4, standoff 0, extent -3.399,1.403 -3,1.797
3D body: height 0.4, standoff 0, extent -2.599,1.403 -2.2,1.797
3D body: height 0.4, standoff 0, extent -1.799,1.403 -1.4,1.797
3D body: height 0.4, standoff 0, extent -0.999,1.403 -0.6,1.797
3D body: height 0.4, standoff 0, extent -0.199,1.403 0.2,1.797
3D body: height 0.4, standoff 0, extent 0.601,1.403 1,1.797
3D body: height 0.4, standoff 0, extent 1.401,1.403 1.8,1.797
3D body: height 0.4, standoff 0, extent 2.201,1.403 2.6,1.797
3D body: height 0.4, standoff 0, extent 3.001,1.403 3.4,1.797
3D body: height 0.4, standoff 0, extent 3.801,1.403 4.2,1.797
3D body: height 0.4, standoff 0, extent 4.601,1.403 5,1.797
3D body: height 0.4, standoff 0, extent 5.401,1.403 5.8,1.797
3D body: height 0.4, standoff 0, extent 6.201,1.403 6.6,1.797
3D body: height 0.4, standoff 0, extent -6.599,0.603 -6.2,0.997
3D body: height 0.4, standoff 0, extent -5.799,0.603 -5.4,0.997
3D body: height 0.4, standoff 0, extent -4.999,0.603 -4.6,0.997
3D body: height 0.4, standoff 0, extent -4.199,0.603 -3.8,0.997
3D body: height 0.4, standoff 0, extent -3.399,0.603 -3,0.997
3D body: height 0.4, standoff 0, extent -2.599,0.603 -2.2,0.997
3D body: height 0.4, standoff 0, extent -1.799,0.603 -1.4,0.997
3D body: height 0.4, standoff 0, extent -0.999,0.603 -0.6,0.997
3D body: height 0.4, standoff 0, extent -0.199,0.603 0.2,0.997
3D body: height 0.4, standoff 0, extent 0.601,0.603 1,0.997
3D body: height 0.4, standoff 0, extent 1.401,0.603 1.8,0.997
3D body: height 0.4, standoff 0, extent 2.201,0.603 2.6,0.997
3D body: height 0.4, standoff 0, extent 3.001,0.603 3.4,0.997
3D body: height 0.4, standoff 0, extent 3.801,0.603 4.2,0.997
3D body: height 0.4, standoff 0, extent 4.601,0.603 5,0.997
3D body: height 0.4, standoff 0, extent 5.401,0.603 5.8,0.997
3D body: height 0.4, standoff 0, extent 6.201,0.603 6.6,0.997
3D body: height 0.4, standoff 0, extent -6.599,-0.197 -6.2,0.197
3D body: height 0.4, standoff 0, extent -5.799,-0.197 -5.4,0.197
3D body: height 0.4, standoff 0, extent -4.999,-0.197 -4.6,0.197
3D body: height 0.4, standoff 0, extent -4.199,-0.197 -3.8,0.197
3D body: height 0.4, standoff 0, extent -3.399,-0.197 -3,0.197
3D body: height 0.4, standoff 0, extent -2.599,-0.197 -2.2,0.197
3D body: height 0.4, standoff 0, extent -1.799,-0.197 -1.4,0.197
3D body: height 0.4, standoff 0, extent -0.999,-0.197 -0.6,0.197
3D body: height 0.4, standoff 0, extent -0.199,-0.197 0.2,0.197
3D body: height 0.4, standoff 0, extent 0.601,-0.197 1,0.197
3D body: height 0.4, standoff 0, extent 1.401,-0.197 1.8,0.197
3D body: height 0.4, standoff 0, extent 2.201,-0.197 2.6,0.197
3D body: height 0.4, standoff 0, extent 3.001,-0.197 3.4,0.197
3D body: height 0.4, standoff 0, extent 3.801,-0.197 4.2,0.197
3D body: height 0.4, standoff 0, extent 4.601,-0.197 5,0.197
3D body: height 0.4, standoff 0, extent 5.401,-0.197 5.8,0.197
3D body: height 0.4, standoff 0, extent 6.201,-0.197 6.6,0.197
3D body: height 0.4, standoff 0, extent -6.599,-0.997 -6.2,-0.603
3D body: height 0.4, standoff 0, extent -5.799,-0.997 -5.4,-0.603
3D body: height 0.4, standoff 0, extent -4.999,-0.997 -4.6,-0.603
3D body: height 0.4, standoff 0, extent -4.199,-0.997 -3.8,-0.603
3D body: height 0.4, standoff 0, extent -3.399,-0.997 -3,-0.603
3D body: height 0.4, standoff 0, extent -2.599,-0.997 -2.2,-0.603
3D body: height 0.4, standoff 0, extent -1.799,-0.997 -1.4,-0.603
3D body: height 0.4, standoff 0, extent -0.999,-0.997 -0.6,-0.603
3D body: height 0.4, standoff 0, extent -0.199,-0.997 0.2,-0.603
3D body: height 0.4, standoff 0, extent 0.601,-0.997 1,-0.603
3D body: height 0.4, standoff 0, extent 1.401,-0.997 1.8,-0.603
3D body: height 0.4, standoff 0, extent 2.201,-0.997 2.6,-0.603
3D body: height 0.4, standoff 0, extent 3.001,-0.997 3.4,-0.603
3D body: height 0.4, standoff 0, extent 3.801,-0.997 4.2,-0.603
3D body: height 0.4, standoff 0, extent 4.601,-0.997 5,-0.603
3D body: height 0.4, standoff 0, extent 5.401,-0.997 5.8,-0.603
3D body: height 0.4, standoff 0, extent 6.201,-0.997 6.6,-0.603
3D body: height 0.4, standoff 0, extent -6.599,-1.797 -6.2,-1.403
3D body: height 0.4, standoff 0, extent -5.799,-1.797 -5.4,-1.403
3D body: height 0.4, standoff 0, extent -4.999,-1.797 -4.6,-1.403
3D body: height 0.4, standoff 0, extent -4.199,-1.797 -3.8,-1.403
3D body: height 0.4, standoff 0, extent -3.399,-1.797 -3,-1.403
3D body: height 0.4, standoff 0, extent -2.599,-1.797 -2.2,-1.403
3D body: height 0.4, standoff 0, extent -1.799,-1.797 -1.4,-1.403
3D body: height 0.4, standoff 0, extent -0.999,-1.797 -0.6,-1.403
3D body: height 0.4, standoff 0, extent -0.199,-1.797 0.2,-1.403
3D body: height 0.4, standoff 0, extent 0.601,-1.797 1,-1.403
3D body: height 0.4, standoff 0, extent 1.401,-1.797 1.8,-1.403
3D body: height 0.4, standoff 0, extent 2.201,-1.797 2.6,-1.403
3D body: height 0.4, standoff 0, extent 3.001,-1.797 3.4,-1.403
3D body: height 0.4, standoff 0, extent 3.801,-1.797 4.2,-1.403
3D body: height 0.4, standoff 0, extent 4.601,-1.797 5,-1.403
3D body: height 0.4, standoff 0, extent 5.401,-1.797 5.8,-1.403
3D body: height 0.4, standoff 0, extent 6.201,-1.797 6.6,-1.403
3D body: height 0.4, standoff 0, extent -6.599,-2.597 -6.2,-2.203
3D body: height 0.4, standoff 0, extent -5.799,-2.597 -5.4,-2.203
3D body: height 0.4, standoff 0, extent -4.999,-2.597 -4.6,-2.203
3D body: height 0.4, standoff 0, extent -4.199,-2.597 -3.8,-2.203
3D body: height 0.4, standoff 0, extent -3.399,-2.597 -3,-2.203
3D body: height 0.4, standoff 0, extent -2.599,-2.597 -2.2,-2.203
3D body: height 0.4, standoff 0, extent -1.799,-2.597 -1.4,-2.203
3D body: height 0.4, standoff 0, extent -0.999,-2.597 -0.6,-2.203
3D body: height 0.4, standoff 0, extent -0.199,-2.597 0.2,-2.203
3D body: height 0.4, standoff 0, extent 0.601,-2.597 1,-2.203
3D body: height 0.4, standoff 0, extent 1.401,-2.597 1.8,-2.203
3D body: height 0.4, standoff 0, extent 2.201,-2.597 2.6,-2.203
3D body: height 0.4, standoff 0, extent 3.001,-2.597 3.4,-2.203
3D body: height 0.4, standoff 0, extent 3.801,-2.597 4.2,-2.203
3D body: height 0.4, standoff 0, extent 4.601,-2.597 5,-2.203
3D body: height 0.4, standoff 0, extent 5.401,-2.597 5.8,-2.203
3D body: height 0.4, standoff 0, extent 6.201,-2.597 6.6,-2.203
3D body: height 0.4, standoff 0, extent -6.599,-3.397 -6.2,-3.003
3D body: height 0.4, standoff 0, extent -5.799,-3.397 -5.4,-3.003
3D body: height 0.4, standoff 0, extent -4.999,-3.397 -4.6,-3.003
3D body: height 0.4, standoff 0, extent -4.199,-3.397 -3.8,-3.003
3D body: height 0.4, standoff 0, extent -3.399,-3.397 -3,-3.003
3D body: height 0.4, standoff 0, extent -2.599,-3.397 -2.2,-3.003
3D body: height 0.4, standoff 0, extent -1.799,-3.397 -1.4,-3.003
3D body: height 0.4, standoff 0, extent -0.999,-3.397 -0.6,-3.003
3D body: height 0.4, standoff 0, extent -0.199,-3.397 0.2,-3.003
3D body: height 0.4, standoff 0, extent 0.601,-3.397 1,-3.003
3D body: height 0.4, standoff 0, extent 1.401,-3.397 1.8,-3.003
3D body: height 0.4, standoff 0, extent 2.201,-3.397 2.6,-3.003
3D body: height 0.4, standoff 0, extent 3.001,-3.397 3.4,-3.003
3D body: height 0.4, standoff 0, extent 3.801,-3.397 4.2,-3.003
3D body: height 0.4, standoff 0, extent 4.601,-3.397 5,-3.003
3D body: height 0.4, standoff 0, extent 5.401,-3.397 5.8,-3.003
3D body: height 0.4, standoff 0, extent 6.201,-3.397 6.6,-3.003
3D body: height 0.4, standoff 0, extent -6.599,-4.197 -6.2,-3.803
3D body: height 0.4, standoff 0, extent -5.799,-4.197 -5.4,-3.803
3D body: height 0.4, standoff 0, extent -4.999,-4.197 -4.6,-3.803
3D body: height 0.4, standoff 0, extent -4.199,-4.197 -3.8,-3.803
3D body: height 0.4, standoff 0, extent -3.399,-4.197 -3,-3.803
3D body: height 0.4, standoff 0, extent -2.599,-4.197 -2.2,-3.803
3D body: height 0.4, standoff 0, extent -1.799,-4.197 -1.4,-3.803
3D body: height 0.4, standoff 0, extent -0.999,-4.197 -0.6,-3.803
3D body: height 0.4, standoff 0, extent -0.199,-4.197 0.2,-3.803
3D body: height 0.4, standoff 0, extent 0.601,-4.197 1,-3.803
3D body: height 0.4, standoff 0, extent 1.401,-4.197 1.8,-3.803
3D body: height 0.4, standoff 0, extent 2.201,-4.197 2.6,-3.803
3D body: height 0.4, standoff 0, extent 3.001,-4.197 3.4,-3.803
3D body: height 0.4, standoff 0, extent 3.801,-4.197 4.2,-3.803
3D body: height 0.4, standoff 0, extent 4.601,-4.197 5,-3.803
3D body: height 0.4, standoff 0, extent 5.401,-4.197 5.8,-3.803
3D body: height 0.4, standoff 0, extent 6.201,-4.197 6.6,-3.803
3D body: height 0.4, standoff 0, extent -6.599,-4.997 -6.2,-4.603
3D body: height 0.4, standoff 0, extent -5.799,-4.997 -5.4,-4.603
3D body: height 0.4, standoff 0, extent -4.999,-4.997 -4.6,-4.603
3D body: height 0.4, standoff 0, extent -4.199,-4.997 -3.8,-4.603
3D body: height 0.4, standoff 0, extent -3.399,-4.997 -3,-4.603
3D body: height 0.4, standoff 0, extent -2.599,-4.997 -2.2,-4.603
3D body: height 0.4, standoff 0, extent -1.799,-4.997 -1.4,-4.603
3D body: height 0.4, standoff 0, extent -0.999,-4.997 -0.6,-4.603
3D body: height 0.4, standoff 0, extent -0.199,-4.997 0.2,-4.603
3D body: height 0.4, standoff 0, extent 0.601,-4.997 1,-4.603
3D body: height 0.4, standoff 0, extent 1.401,-4.997 1.8,-4.603
3D body: height 0.4, standoff 0, extent 2.201,-4.997 2.6,-4.603
3D body: height 0.4, standoff 0, extent 3.001,-4.997 3.4,-4.603
3D body: height 0.4, standoff 0, extent 3.801,-4.997 4.2,-4.603
3D body: height 0.4, standoff 0, extent 4.601,-4.997 5,-4.603
3D body: height 0.4, standoff 0, extent 5.401,-4.997 5.8,-4.603
3D body: height 0.4, standoff 0, extent 6.201,-4.997 6.6,-4.603
3D body: height 0.4, standoff 0, extent -6.599,-5.797 -6.2,-5.403
3D body: height 0.4, standoff 0, extent -5.799,-5.797 -5.4,-5.403
3D body: height 0.4, standoff 0, extent -4.999,-5.797 -4.6,-5.403
3D body: height 0.4, standoff 0, extent -4.199,-5.797 -3.8,-5.403
3D body: height 0.4, standoff 0, extent -3.399,-5.797 -3,-5.403
3D body: height 0.4, standoff 0, extent -2.599,-5.797 -2.2,-5.403
3D body: height 0.4, standoff 0, extent -1.799,-5.797 -1.4,-5.403
3D body: height 0.4, standoff 0, extent -0.999,-5.797 -0.6,-5.403
3D body: height 0.4, standoff 0, extent -0.199,-5.797 0.2,-5.403
3D body: height 0.4, standoff 0, extent 0.601,-5.797 1,-5.403
3D body: height 0.4, standoff 0, extent 1.401,-5.797 1.8,-5.403
3D body: height 0.4, standoff 0, extent 2.201,-5.797 2.6,-5.403
3D body: height 0.4, standoff 0, extent 3.001,-5.797 3.4,-5.403
3D body: height 0.4, standoff 0, extent 3.801,-5.797 4.2,-5.403
3D body: height 0.4, standoff 0, extent 4.601,-5.797 5,-5.403
3D body: height 0.4, standoff 0, extent 5.401,-5.797 5.8,-5.403
3D body: height 0.4, standoff 0, extent 6.201,-5.797 6.6,-5.403
3D body: height 0.4, standoff 0, extent -6.599,-6.597 -6.2,-6.203
3D body: height 0.4, standoff 0, extent -5.799,-6.597 -5.4,-6.203
3D body: height 0.4, standoff 0, extent -4.999,-6.597 -4.6,-6.203
3D body: height 0.4, standoff 0, extent -4.199,-6.597 -3.8,-6.203
3D body: height 0.4, standoff 0, extent -3.399,-6.597 -3,-6.203
3D body: height 0.4, standoff 0, extent -2.599,-6.597 -2.2,-6.203
3D body: height 0.4, standoff 0, extent -1.799,-6.597 -1.4,-6.203
3D body: height 0.4, standoff 0, extent -0.999,-6.597 -0.6,-6.203
3D body: height 0.4, standoff 0, extent -0.199,-6.597 0.2,-6.203
3D body: height 0.4, standoff 0, extent 0.601,-6.597 1,-6.203
3D body: height 0.4, standoff 0, extent 1.401,-6.597 1.8,-6.203
3D body: height 0.4, standoff 0, extent 2.201,-6.597 2.6,-6.203
3D body: height 0.4, standoff 0, extent 3.001,-6.597 3.4,-6.203
3D body: height 0.4, standoff 0, extent 3.801,-6.597 4.2,-6.203
3D body: height 0.4, standoff 0, extent 4.601,-6.597 5,-6.203
3D body: height 0.4, standoff 0, extent 5.401,-6.597 5.8,-6.203
3D body: height 0.4, standoff 0, extent 6.201,-6.597 6.6,-6.203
